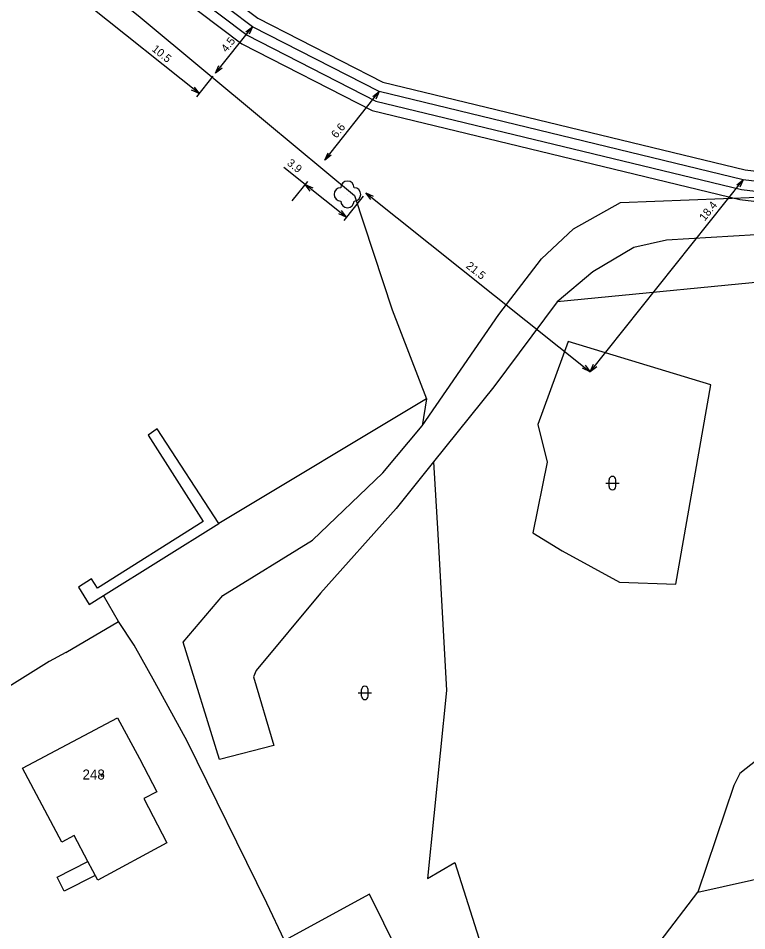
# Model space of a CAD drawing. Extents: x -836739 to -834468, y -1071001 to -1070126.
# Drawn here: x -836580.6 to -836526, y -1070268.6 to -1070200.2 of the extents above; entities that cross this region are included whole.
import ezdxf

# ---------------------------------------------------------------- set-up
doc = ezdxf.new("R2010")
doc.units = 0
for name, color, linetype in [('f001_pol_linie', 7, 'Continuous'), ('f001_pol_texty', 7, 'Continuous'), ('f001_pol_znacky', 7, 'Continuous'), ('f006_osa_trasy', 7, 'Continuous'), ('f006_stp_koty', 7, 'Continuous'), ('f309_trubka', 7, 'Continuous')]:
    doc.layers.add(name, color=color, linetype=linetype)

msp = doc.modelspace()

# ---------------------------------------------------------------- linework, layer by layer
at = {"layer": 'f001_pol_linie'}
for points in [[(-836646.79, -1070164.47), (-836635.17, -1070166.04), (-836623.33, -1070167.88), (-836615.58, -1070169.1), (-836607.83, -1070173.77), (-836593.75, -1070183.78), (-836585.2, -1070189.95), (-836577.96, -1070194.89), (-836571.5, -1070200.08), (-836562.11, -1070207.9), (-836555.43, -1070213.46), (-836552.63, -1070222.02), (-836550.05, -1070228.71)], [(-836565.55, -1070255.75), (-836568.29, -1070246.94), (-836565.3, -1070243.45), (-836558.59, -1070239.29), (-836553.32, -1070234.26), (-836550.36, -1070230.73), (-836544.63, -1070222.38), (-836541.42, -1070218.21), (-836539.02, -1070215.95), (-836535.5, -1070213.99), (-836517.48, -1070213.29), (-836497.22, -1070212.11), (-836494.05, -1070212.5), (-836489.39, -1070214.02), (-836485.93, -1070216.36), (-836482.28, -1070220.4), (-836478.23, -1070227.56), (-836471.79, -1070243.33), (-836465.92, -1070256.62), (-836463.85, -1070260.25), (-836463.13, -1070260.78)], [(-836466.54, -1070263.19), (-836474.56, -1070243.73), (-836478.12, -1070235.21), (-836483.33, -1070224.14), (-836486.58, -1070219.75), (-836489.27, -1070217.57), (-836492.22, -1070215.97), (-836495.08, -1070215.2), (-836498.82, -1070214.84), (-836513.64, -1070215.7), (-836532.05, -1070216.8), (-836534.5, -1070217.36), (-836537.57, -1070219.18), (-836540.24, -1070221.43), (-836545, -1070227.8), (-836549.52, -1070233.43), (-836552.32, -1070236.92), (-836557.98, -1070243.27), (-836562.8, -1070249.08), (-836563.01, -1070249.54), (-836561.48, -1070254.69), (-836565.55, -1070255.75)], [(-836513.64, -1070241.9), (-836520.33, -1070228.24), (-836519.17, -1070223.67), (-836521.79, -1070219.62), (-836540.24, -1070221.43)], [(-836539.88, -1070240.11), (-836535.57, -1070242.46), (-836531.35, -1070242.61), (-836528.72, -1070227.65), (-836539.42, -1070224.41), (-836541.71, -1070230.64), (-836541.01, -1070233.45), (-836542.08, -1070238.74), (-836539.88, -1070240.11)], [(-836550.05, -1070228.71), (-836565.62, -1070238.05)], [(-836550.05, -1070228.71), (-836550.36, -1070230.73)], [(-836575.33, -1070244.13), (-836574.25, -1070243.46), (-836565.62, -1070238.05), (-836570.23, -1070230.95), (-836570.9, -1070231.42), (-836566.79, -1070237.89), (-836574.71, -1070242.91), (-836575.15, -1070242.2), (-836576.12, -1070242.83), (-836575.33, -1070244.13)], [(-836549.52, -1070233.43), (-836549.19, -1070238.84), (-836548.54, -1070250.58), (-836549.98, -1070264.67), (-836547.91, -1070263.48), (-836544.14, -1070275.36), (-836540.5, -1070282.59), (-836537.68, -1070276.1), (-836535.35, -1070273.1), (-836529.71, -1070265.69)], [(-836571.95, -1070247.18), (-836573.14, -1070245.4), (-836574.25, -1070243.46)], [(-836577.07, -1070247.73), (-836573.14, -1070245.4)], [(-836570.4, -1070249.95), (-836571.95, -1070247.18)], [(-836577.07, -1070247.73), (-836578.34, -1070248.4), (-836584.63, -1070252.32), (-836586.94, -1070253.69)], [(-836562.01, -1070266.51), (-836567.99, -1070254.38), (-836570.4, -1070249.95)], [(-836574.69, -1070264.8), (-836575.43, -1070263.4), (-836576.45, -1070261.45), (-836577.39, -1070261.94), (-836580.33, -1070256.39), (-836573.21, -1070252.62), (-836571.55, -1070255.68), (-836570.27, -1070258.18), (-836571.22, -1070258.68), (-836569.51, -1070262.01), (-836574.69, -1070264.8)], [(-836522.78, -1070253.83), (-836526.55, -1070256.8), (-836527.02, -1070257.7), (-836529.71, -1070265.69)], [(-836529.71, -1070265.69), (-836519.75, -1070263.47), (-836511.22, -1070260.9), (-836508.71, -1070259.23)], [(-836574.88, -1070264.44), (-836577.21, -1070265.61), (-836577.74, -1070264.57), (-836575.43, -1070263.4)], [(-836544.78, -1070284.68), (-836548.9, -1070276.83), (-836554.31, -1070265.85), (-836560.69, -1070269.33)], [(-836560.69, -1070269.33), (-836562.01, -1070266.51)]]:
    msp.add_lwpolyline(points, dxfattribs=at)
at = {"layer": 'f001_pol_znacky'}
for p, q in [((-836536.36, -1070235.27), (-836536.36, -1070234.77)), ((-836535.86, -1070235.27), (-836535.86, -1070234.77)), ((-836536.61, -1070235.02), (-836535.61, -1070235.02)), ((-836554.91, -1070251.01), (-836554.91, -1070250.51)), ((-836554.41, -1070251.01), (-836554.41, -1070250.51)), ((-836555.16, -1070250.76), (-836554.16, -1070250.76))]:
    msp.add_line(p, q, dxfattribs=at)
for centre, radius in [((-836555.97, -1070213.37), 0.0005), ((-836574.35, -1070256.93), 0.0875)]:
    msp.add_circle(centre, radius, dxfattribs=at)
for centre, radius, start, end in [((-836556.47, -1070213.37), 0.5, 89.99999, 269.99999), ((-836555.97, -1070212.87), 0.5, 0, 179.99999), ((-836555.47, -1070213.37), 0.5, 270, 89.99999), ((-836555.97, -1070213.87), 0.5, 179.99999, 359.99999), ((-836536.11, -1070234.77), 0.25, 0, 179.99999), ((-836536.11, -1070235.27), 0.25, 179.99999, 359.99999), ((-836554.66, -1070250.51), 0.25, 0, 179.99999), ((-836554.66, -1070251.01), 0.25, 179.99999, 359.99999)]:
    msp.add_arc(centre, radius, start, end, dxfattribs=at)
at = {"layer": 'f006_osa_trasy'}
msp.add_lwpolyline([(-836471.29, -1070247.06), (-836475.13, -1070240.07), (-836481.69, -1070223.19), (-836484.06, -1070219.25), (-836486.31, -1070218.35), (-836503.86, -1070214.94), (-836526.3, -1070212.27), (-836553.58, -1070205.67), (-836563.09, -1070200.8), (-836595.87, -1070176.09), (-836614.86, -1070165.34), (-836629.43, -1070164.09), (-836642.16, -1070162.86), (-836653.58, -1070160.22), (-836662.77, -1070161.03), (-836672.46, -1070165.03), (-836697.35, -1070176), (-836703.68, -1070184.13), (-836710.27, -1070188.76)], dxfattribs=at)
at = {"layer": 'f006_stp_koty'}
for points in [[(-836567.09, -1070205.818), (-836575.306, -1070199.268)], [(-836565.864, -1070204.28), (-836563.09, -1070200.8)], [(-836563.581, -1070201.175), (-836563.09, -1070200.8), (-836563.346, -1070201.362)], [(-836565.372, -1070203.904), (-836565.864, -1070204.28), (-836565.607, -1070203.717)], [(-836566.051, -1070204.514), (-836567.277, -1070206.052)], [(-836567.465, -1070205.326), (-836567.09, -1070205.818), (-836567.652, -1070205.561)], [(-836557.676, -1070210.808), (-836553.58, -1070205.67)], [(-836554.071, -1070206.045), (-836553.58, -1070205.67), (-836553.836, -1070206.232)], [(-836557.184, -1070210.432), (-836557.676, -1070210.808), (-836557.419, -1070210.245)], [(-836556.054, -1070215.085), (-836560.739, -1070211.35)], [(-836537.78, -1070226.67), (-836526.3, -1070212.27)], [(-836526.791, -1070212.645), (-836526.3, -1070212.27), (-836526.556, -1070212.832)], [(-836560.107, -1070213.857), (-836558.943, -1070212.398)], [(-836558.754, -1070213.123), (-836559.13, -1070212.632), (-836558.567, -1070212.888)], [(-836554.786, -1070213.494), (-836556.241, -1070215.319)], [(-836554.6, -1070213.26), (-836537.78, -1070226.669)], [(-836554.224, -1070213.751), (-836554.6, -1070213.26), (-836554.037, -1070213.516)], [(-836556.429, -1070214.593), (-836556.054, -1070215.085), (-836556.616, -1070214.828)], [(-836538.155, -1070226.177), (-836537.78, -1070226.669), (-836538.342, -1070226.412)], [(-836537.288, -1070226.294), (-836537.78, -1070226.67), (-836537.523, -1070226.107)]]:
    msp.add_lwpolyline(points, dxfattribs=at)
at = {"layer": 'f309_trubka'}
for points in [[(-836710.701, -1070188.146), (-836710.087, -1070187.715), (-836704.203, -1070183.581), (-836697.826, -1070175.39), (-836672.754, -1070164.34), (-836662.95, -1070160.293), (-836653.527, -1070159.462), (-836642.039, -1070162.118), (-836629.362, -1070163.343), (-836614.633, -1070164.607), (-836595.458, -1070175.462), (-836562.69, -1070200.162), (-836553.317, -1070204.962), (-836526.167, -1070211.531), (-836503.744, -1070214.199), (-836486.097, -1070217.627), (-836483.547, -1070218.647), (-836481.014, -1070222.858), (-836474.449, -1070239.752), (-836470.632, -1070246.7)], [(-836471.29, -1070247.06), (-836475.13, -1070240.07), (-836481.69, -1070223.19), (-836484.06, -1070219.25), (-836486.31, -1070218.35), (-836503.86, -1070214.94), (-836526.3, -1070212.27), (-836553.58, -1070205.67), (-836563.09, -1070200.8), (-836595.87, -1070176.09), (-836614.86, -1070165.34), (-836629.43, -1070164.09), (-836642.16, -1070162.86), (-836653.58, -1070160.22), (-836662.77, -1070161.03), (-836672.46, -1070165.03), (-836697.35, -1070176), (-836703.68, -1070184.13), (-836709.656, -1070188.329), (-836710.27, -1070188.76)], [(-836709.839, -1070189.374), (-836709.225, -1070188.943), (-836703.157, -1070184.679), (-836696.874, -1070176.61), (-836672.166, -1070165.72), (-836662.59, -1070161.767), (-836653.633, -1070160.978), (-836642.281, -1070163.602), (-836629.498, -1070164.837), (-836615.087, -1070166.073), (-836596.282, -1070176.718), (-836563.49, -1070201.438), (-836553.843, -1070206.378), (-836526.433, -1070213.009), (-836503.976, -1070215.681), (-836486.523, -1070219.073), (-836484.573, -1070219.853), (-836482.366, -1070223.522), (-836475.811, -1070240.388), (-836471.948, -1070247.42)], [(-836709.408, -1070189.988), (-836708.794, -1070189.557), (-836702.634, -1070185.228), (-836696.398, -1070177.22), (-836671.872, -1070166.41), (-836662.41, -1070162.504), (-836653.686, -1070161.736), (-836642.402, -1070164.344), (-836629.566, -1070165.584), (-836615.314, -1070166.806), (-836596.694, -1070177.346), (-836563.89, -1070202.076), (-836554.106, -1070207.086), (-836526.566, -1070213.748), (-836504.092, -1070216.422), (-836486.736, -1070219.796), (-836485.086, -1070220.456), (-836483.042, -1070223.854), (-836476.492, -1070240.706), (-836472.606, -1070247.78)]]:
    msp.add_lwpolyline(points, dxfattribs=at)

# ---------------------------------------------------------------- texts
at = {"layer": 'f001_pol_texty'}
msp.add_text('248', height=0.75, dxfattribs=at).set_placement((-836575.83, -1070257.25))
at = {"layer": 'f006_stp_koty'}
for s, rotation, p in [('4.5', 51.44, (-836565.034, -1070202.758)), ('10.5', 321.44, (-836570.685, -1070202.566)), ('6.6', 51.44, (-836556.783, -1070209.207)), ('3.9', 321.44, (-836560.551, -1070211.116)), ('18.4', 51.44, (-836529.189, -1070215.413)), ('21.5', 321.44, (-836547.133, -1070218.828))]:
    msp.add_text(s, height=0.6, rotation=rotation, dxfattribs=at).set_placement(p)

doc.saveas('drawing.dxf')
